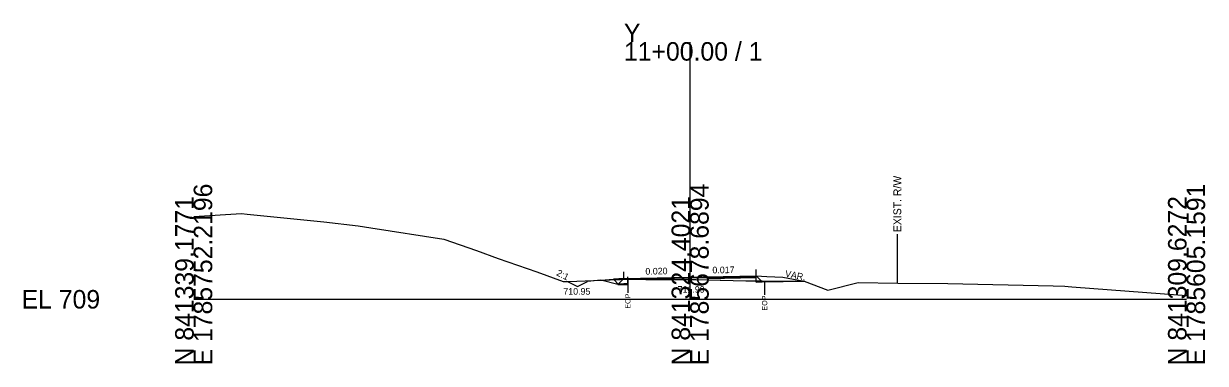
# Model space of a CAD drawing. Extents: x -26 to 153, y 990 to 3546.
# Drawn here: x -25.7 to 152.8, y 1990.3 to 2041.7 of the extents above; entities that cross this region are included whole.
import ezdxf

# ---------------------------------------------------------------- set-up
doc = ezdxf.new("R2010")
doc.units = 0
for name, color, linetype in [('Exist Cross Section Cell', 7, 'Continuous'), ('Exist XS Center Line Elevation Label', 7, 'Continuous'), ('Exist XS Ground Line', 7, 'Continuous'), ('Old_Level_10', 7, 'Continuous'), ('Prop XS DDE', 7, 'Continuous'), ('Prop XS Ditch Slope Text', 7, 'Continuous'), ('Prop XS Ditch Standard Text', 7, 'Continuous'), ('Prop XS Earthwork Shape', 7, 'Continuous'), ('Prop XS EOT Tick Mark', 7, 'Continuous'), ('Prop XS Finish Grade', 7, 'Continuous'), ('Prop XS Finish Grade Pavement', 7, 'Continuous'), ('Prop XS Hydro Typical Ditch Data', 7, 'Continuous'), ('Prop XS Pvmt Edge Slope', 7, 'Continuous'), ('Prop XS SE Text', 7, 'Continuous'), ('Prop XS Subgrade Earthwork', 7, 'Continuous'), ('Scratch_Level_6', 7, 'Continuous')]:
    doc.layers.add(name, color=color, linetype=linetype)

msp = doc.modelspace()

# ---------------------------------------------------------------- linework, layer by layer
at = {"layer": 'Exist Cross Section Cell'}
for p, q in [((75, 2000), (75, 2038.88)), ((0, 2000), (75, 2000)), ((75, 2000), (150, 2000))]:
    msp.add_line(p, q, dxfattribs=at)
at = {"layer": 'Exist XS Ground Line'}
msp.add_lwpolyline([(0, 2012.51), (7.23, 2012.96), (8.09, 2012.89), (19.67, 2011.72), (24.85, 2011.1), (26.78, 2010.79), (37.78, 2009.07), (42.74, 2007.36), (46.01, 2006.17), (51.86, 2004.16), (55.84, 2002.68), (56.64, 2002.7), (65.46, 2003.02), (68.33, 2003.01), (75, 2002.99), (75.86, 2002.98), (83.43, 2002.8), (86.15, 2002.76), (89.2, 2002.72), (92.23, 2002.72), (95.8, 2001.39), (100.37, 2002.56), (106.38, 2002.46), (113.93, 2002.39), (129.87, 2002.01), (131.63, 2001.96), (132.09, 2001.94), (132.67, 2001.86), (149.32, 2000.6), (150, 2000.58)], dxfattribs=at)
at = {"layer": 'Old_Level_10'}
for p, q in [((106.3, 2009.86), (106.3, 2002.46)), ((65.58, 2003.02), (65.58, 2000.97)), ((86.26, 2002.72), (86.26, 2000.67))]:
    msp.add_line(p, q, dxfattribs=at)
at = {"layer": 'Prop XS DDE'}
for p, q in [((56.49, 2002.69), (57.97, 2001.95)), ((57.97, 2001.95), (59.51, 2002.71)), ((61.5, 2002.87), (59.51, 2002.71))]:
    msp.add_line(p, q, dxfattribs=at)
at = {"layer": 'Prop XS Earthwork Shape'}
for points in [[(64.06, 2002.22), (61.5, 2002.87), (65.46, 2003.02), (65.58, 2003.02), (65.58, 2002.25)], [(65, 2002.32), (64.15, 2002.3), (63.51, 2002.95), (65.46, 2003.02), (65.58, 2003.02), (65.58, 2002.33)], [(85.82, 2002.7), (85.88, 2002.76), (85, 2002.78), (85, 2002.69)], [(85, 2002.6), (85, 2002.78), (86.15, 2002.76), (89.2, 2002.72), (92.23, 2002.72), (85.9, 2002.62)]]:
    msp.add_lwpolyline(points, close=True, dxfattribs=at)
at = {"layer": 'Prop XS EOT Tick Mark'}
for p, q in [((65, 2003.15), (65, 2004.15)), ((85, 2003.52), (85, 2004.52))]:
    msp.add_line(p, q, dxfattribs=at)
at = {"layer": 'Prop XS Finish Grade'}
for p, q in [((65, 2003.15), (63.43, 2003.03)), ((85, 2003.52), (86.57, 2003.45)), ((86.57, 2003.45), (89, 2003.35)), ((89, 2003.35), (92.23, 2002.72)), ((61.5, 2002.87), (63.43, 2003.03))]:
    msp.add_line(p, q, dxfattribs=at)
at = {"layer": 'Prop XS Finish Grade Pavement'}
for p, q in [((65, 2003.15), (75, 2003.35)), ((75, 2003.35), (85, 2003.52))]:
    msp.add_line(p, q, dxfattribs=at)
at = {"layer": 'Prop XS Hydro Typical Ditch Data'}
msp.add_line((89, 2003.35), (92.23, 2002.72), dxfattribs=at)
at = {"layer": 'Prop XS Pvmt Edge Slope'}
for p, q in [((65, 2003.15), (64.06, 2002.22)), ((85, 2003.52), (85.9, 2002.62))]:
    msp.add_line(p, q, dxfattribs=at)
at = {"layer": 'Prop XS Subgrade Earthwork'}
for p, q in [((64.06, 2002.22), (61.5, 2002.87)), ((64.06, 2002.22), (65.58, 2002.25)), ((65.58, 2002.25), (65.58, 2003.02)), ((65.58, 2002.25), (65.58, 2003.02)), ((85, 2002.6), (85, 2002.78)), ((85, 2002.6), (85.9, 2002.62)), ((85.9, 2002.62), (92.23, 2002.72))]:
    msp.add_line(p, q, dxfattribs=at)
at = {"layer": 'Scratch_Level_6'}
for p, q in [((65.58, 2003.02), (65.58, 2003.37)), ((65.58, 2003.04), (75, 2003.23)), ((75, 2003.23), (65.58, 2003.04)), ((75, 2003.23), (85, 2003.4)), ((85, 2003.4), (75, 2003.23)), ((77.84, 2003.15), (77.63, 2002.94)), ((77.63, 2002.94), (77.84, 2003.15)), ((77.84, 2003.15), (77.63, 2002.94)), ((77.84, 2003.15), (85, 2003.27)), ((77.84, 2003.15), (85, 2003.27)), ((85, 2003.27), (77.84, 2003.15)), ((85, 2002.78), (85, 2004.03)), ((85, 2003.27), (85, 2003.4)), ((85, 2002.78), (85, 2003.27)), ((65.58, 2003.04), (65.58, 2003.02)), ((77.63, 2002.94), (83.43, 2002.8)), ((83.43, 2002.8), (85, 2002.78))]:
    msp.add_line(p, q, dxfattribs=at)
msp.add_lwpolyline([(65.58, 2003.02), (68.33, 2003.01), (75, 2002.99), (75.86, 2002.98), (77.63, 2002.94)], dxfattribs=at)

# ---------------------------------------------------------------- texts
at = {"layer": 'Exist Cross Section Cell'}
for s, p in [('Y', (65, 2038.88)), ('11+00.00 / 1', (65, 2036.08)), ('EL 709', (-26, 1998.6))]:
    msp.add_text(s, height=2.8, dxfattribs=at).set_placement(p)
for s, p in [('E 1785752.2196', (2.8, 1990)), ('E 1785678.6894', (77.8, 1990)), ('E 1785605.1591', (152.8, 1990)), ('N 841339.1771', (0, 1990)), ('N 841324.4021', (75, 1990)), ('N 841309.6272', (150, 1990))]:
    msp.add_text(s, height=2.8, rotation=90, dxfattribs=at).set_placement(p)
at = {"layer": 'Exist XS Center Line Elevation Label'}
msp.add_text('711.99', height=1, dxfattribs=at).set_placement((73.11, 2000.99))
at = {"layer": 'Old_Level_10'}
for s, height, p in [('EXIST. R/W', 1.181, (106.89, 2010.16)), ('EOP', 0.787, (65.98, 1998.57)), ('EOP', 0.787, (86.65, 1998.28))]:
    msp.add_text(s, height=height, rotation=90, dxfattribs=at).set_placement(p)
at = {"layer": 'Prop XS Ditch Slope Text'}
for s, rotation, p in [('2:1', 333.4349, (54.71, 2003.66)), ('VAR.', 349.0833, (89.28, 2003.42))]:
    msp.add_text(s, height=1, rotation=rotation, dxfattribs=at).set_placement(p)
at = {"layer": 'Prop XS Ditch Standard Text'}
msp.add_text('710.95', height=1, dxfattribs=at).set_placement((55.84, 2000.69))
at = {"layer": 'Prop XS SE Text'}
for s, rotation, p in [('0.017', 0.9548, (78.37, 2003.91)), ('0.020', 1.1458, (68.25, 2003.72))]:
    msp.add_text(s, height=1, rotation=rotation, dxfattribs=at).set_placement(p)

doc.saveas('drawing.dxf')
